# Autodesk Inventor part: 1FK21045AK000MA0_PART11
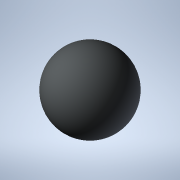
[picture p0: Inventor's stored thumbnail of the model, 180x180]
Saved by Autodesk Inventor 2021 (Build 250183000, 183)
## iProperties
Created: 2025-04
Part Number: 1FK21045AK000MA0_PART11
Material: Generic
Catalog Web Link: www.3dfindit.com
Description: -Servo synchronous motor
Document SubType Name: Modeling
Designer: psAdmin
Mass: 0.137258 g
Surface Area: 1.2868 cm^2
Volume: 0.137258 cm^3
Density: 1 g/cm^3
Appearance: PSOLRGB-212-217-219
Category: PARTsolutions
Title: 1FK21045AK000MA0_PART11
Author: Cadenas PARTsolutions
Comments: Servo synchronous motor
Sending System: PARTsolutions
Preprocessor: ST-DEVELOPER v19.3
PSOL_IDENT_0: {$CADENAS_DATA/23d-libs/siemens_ag/_cat_/3d/2f/1fk21045ak000ma0.prj},216 {VTYP=3D},{NB=1FK21045AK000
PSOL_IDENT_1: MA0_PART11},{LINA=1FK21045AK000MA0_PART11},{NN=1FK21045AK000MA0_PART11},{NOPRJ=TRUE},{DATE=19.08.202
PSOL_IDENT_2: 5 14:00:34},{GEOMDATE=30.07.2025 02:01:24},{VERSION=},{LINEID=10},{WBVAR=},{WBNUMERIC=}  {NB=1FK2104
PSOL_IDENT_3: 5AK000MA0_PART11},{LINA=1FK21045AK000MA0_PART11},{KT=DUMMY},{PREVIEW=../../../_pool_/a9/69/p_d211_xx
PSOL_IDENT_4: _00818j.png},{DESCSHORT=SIMOTICS S-1FK2 HD, SINAMICS S210 3AC 400V-480V, 1.7 Nm, 6000 rpm},{DESCLONG=
PSOL_IDENT_5: SIMOTICS S-1FK2 HD servo motor M0=2.4 Nm; PN = 1.07 kW at nN=6000 rpm (380-480 V); PN = 0.75 kW at n
PSOL_IDENT_6: N=3000 rpm (200-240 V); degree of protection IP64; cylindrical shaft D19x40mm; absolute encoder 22-b
PSOL_IDENT_7: it + 12-bit multiturn (encoder AM22DQC); with OCC interface; plug size M17, rotatable; SIMOTICS S-1F
PSOL_IDENT_8: K2 servomotorfor a wide range of uses in industrial environments. SIMOTICS S‑1FK2 servomotors are co
PSOL_IDENT_9: mpact synchronous motors with a high dynamic performance that set themselves apart as a result of th
PSOL_IDENT_10: eir high power density, degree of protection and overload capability. The motors are available in tw
PSOL_IDENT_11: o variants: as High Dynamic variant (highest dynamic performance as a result of the low intrinsic mo
PSOL_IDENT_12: ment of inertia for applications demanding a high dynamic performance with low moved masses) - and a
PSOL_IDENT_13: s Compact variant (precise and stable closed-loop control for medium up to large moved masses as a r
PSOL_IDENT_14: esult of a medium intrinsic moment of inertia). SIMOTICSS‑1FK2 servomotors fully exploit their stren
PSOL_IDENT_15: gths in a system with the SINAMICSS210 frequency converter and simple connection using the one cable
PSOL_IDENT_16: connection (OCC). Advantages include the short control and positioning times, fast and precise corr
PSOL_IDENT_17: ection of disturbing quantities as well as stable control with a high dynamic performance. The servo
PSOL_IDENT_18: motors can be configured to address a wide range of requirements. For example with and without hold
PSOL_IDENT_19: ing brake, IP64 or IP65 degree of protection, singleturn or multiturn absolute encoders - to name ju
PSOL_IDENT_20: st a few. Further, the servomotors are available in different shaft heights extending from 20 to 100
PSOL_IDENT_21: . A shaft sealing ring is available to achieve an IP65 degree of protection and for subsequent mount
PSOL_IDENT_22: ing at the motor or as spare part. SIMOTICS - the optimum motor for each and every motion control ap
PSOL_IDENT_23: plication.},{INTNO=804766789342},{SUPPLIERALTNO=1FK2104-5AK00-0MA0},{MANUID=1FK21045AK000MA0},{MANUN
PSOL_IDENT_24: AME=Siemens},{MANUTYPEDESC=Synchronous motor 1FK2-HD 2,39 Nm},{AAU732=SIMOTICS},{AAO057=S-1FK2},{AAU
PSOL_IDENT_25: 734=SIMOTICS S-1FK2 HD servo motor M0=2.4 Nm; PN = 1.07 kW at nN=6000 rpm (380-480 V); PN = 0.75 kW
PSOL_IDENT_26: at nN=3000 rpm (200-240 V); degree of protection IP64; cylindrical shaft D19x40mm; absolute encoder
PSOL_IDENT_27: 22-bit + 12-bit multiturn (encoder AM22DQC); with OCC interface; plug size M17, rotatable;},{AAW338=
PSOL_IDENT_28: Synchronous motor 1FK2-HD 2,39 Nm},{AAO742=SIMOTICS},{AAO663=4042948691151},{NOCUPEROU=1},{PRICEQUAN
PSOL_IDENT_29: TITY=1},{QUANTITYMIN=1},{QUANTITYINT=1},{CTN=85015100},{COO=DE},{AAO676=1FK2104-5AK00-0MA0},{AAO677=
PSOL_IDENT_30: Siemens AG},{ORDERUNIT=C62},{CONTENTUNIT=C62}
NB: 1FK21045AK000MA0_PART11
NT: Servo synchronous motor
NBSYN: $MANUID._PART11
LINA: 1FK21045AK000MA0_PART11
CATALOG: SIEMENS
PREVIEW: ../../../_pool_/a9/69/p_d211_xx_00818j.png
DESCSHORT: SIMOTICS S-1FK2 HD, SINAMICS S210 3AC 400V-480V, 1.7 Nm, 6000 rpm
DESCLONG: SIMOTICS S-1FK2 HD servo motor M0=2.4 Nm; PN = 1.07 kW at nN=6000 rpm (380-480 V); PN = 0.75 kW at nN=3000 rpm (200-240 V); degree of protection IP64; cylindric
INTNO: 804766789342
SUPPLIERALTNO: 1FK2104-5AK00-0MA0
MANUID: 1FK21045AK000MA0
MANUNAME: Siemens
MANUTYPEDESC: Synchronous motor 1FK2-HD 2,39 Nm
AAU732: SIMOTICS
AAO057: S-1FK2
AAU734: SIMOTICS S-1FK2 HD servo motor M0=2.4 Nm; PN = 1.07 kW at nN=6000 rpm (380-480 V); PN = 0.75 kW at nN=3000 rpm (200-240 V); degree of protection IP64; cylindric
AAW338: Synchronous motor 1FK2-HD 2,39 Nm
AAO742: SIMOTICS
AAO663: 4042948691151.0
NOCUPEROU: 1
PRICEQUANTITY: 1
QUANTITYMIN: 1
QUANTITYINT: 1
CTN: 85015100
COO: DE
ARTICLENO: 1FK21045AK000MA0_PART11
BOMINFO: 1FK21045AK000MA0_PART11
CREATOR: CADENAS GmbH
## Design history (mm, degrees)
feature "2025_04_17_15_39_51_0728"
body "Solid1"
